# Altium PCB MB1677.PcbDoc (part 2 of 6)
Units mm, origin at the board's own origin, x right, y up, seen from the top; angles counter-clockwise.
Board outline 78 x 105 mm, 6 copper layers (Top Layer, Signal Layer 1, Signal Layer 2, Signal Layer 3, Signal Layer 4, Bottom Layer), stack 1.574 mm thick; 404 components, 325 nets, 1691 pads, 961 vias.
Unrouted connection lines stored in the file: 9.
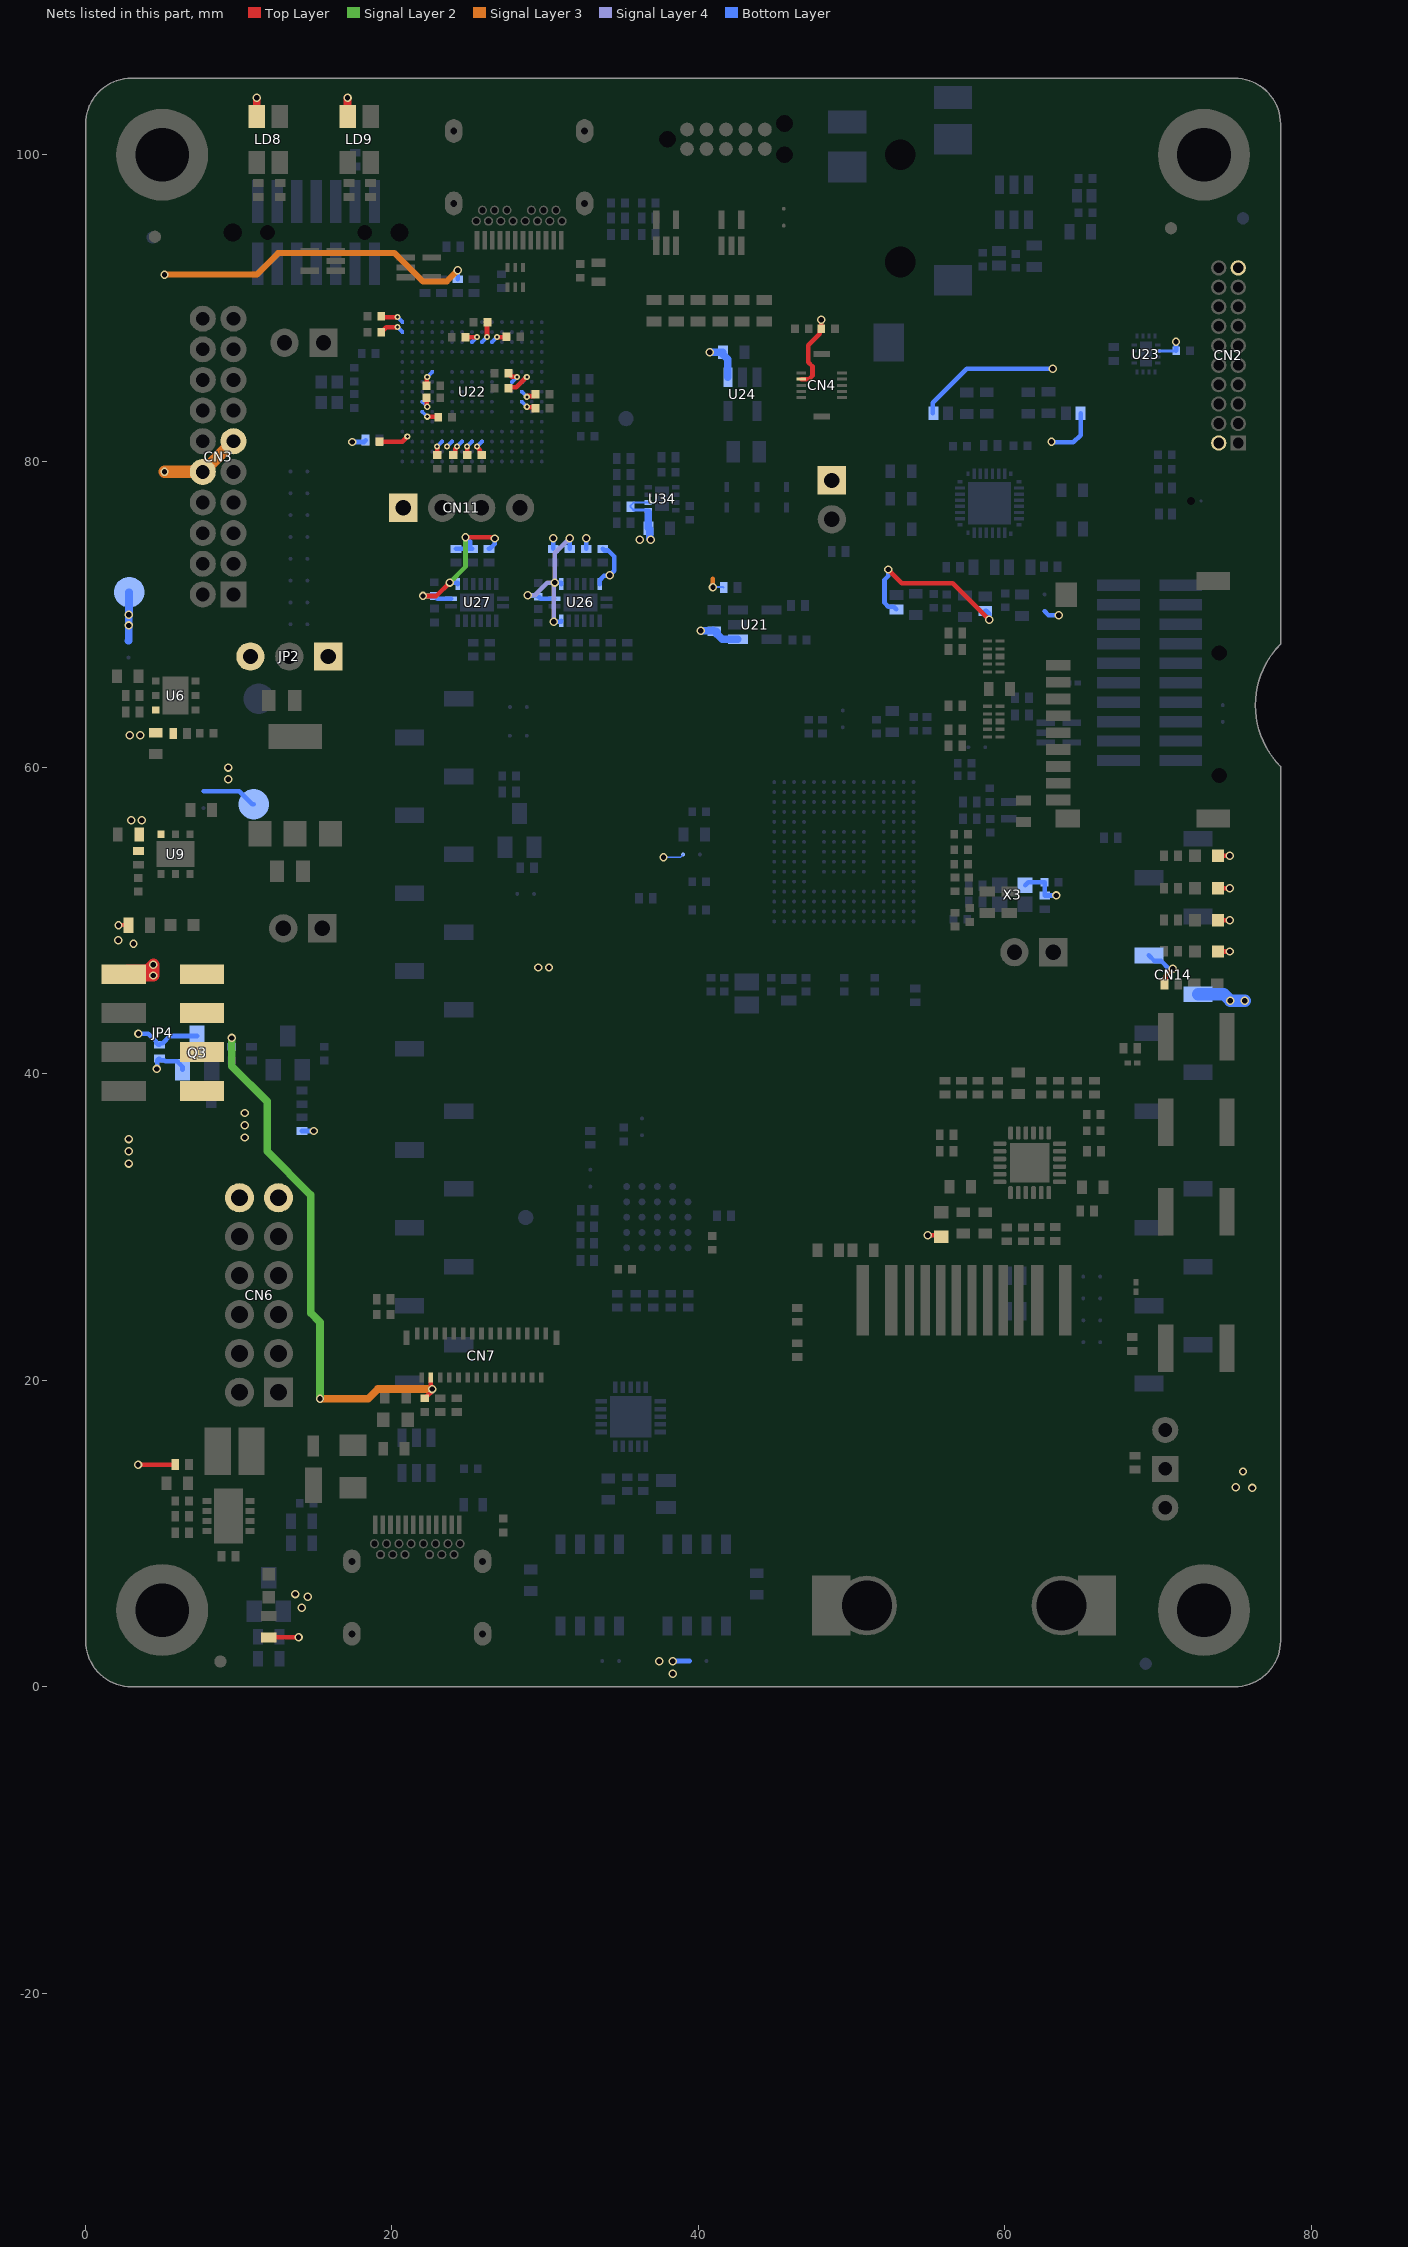
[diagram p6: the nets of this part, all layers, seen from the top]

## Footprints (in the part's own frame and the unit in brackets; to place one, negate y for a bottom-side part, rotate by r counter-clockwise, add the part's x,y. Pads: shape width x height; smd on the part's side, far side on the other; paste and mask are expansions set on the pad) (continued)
ICC_QFN32-EPAD_4X4_P040 [mm] "MCD-03196"
  rect 0.22x0.3 smd mask+0.05: 1(-1.4,-2) 8(1.4,-1.925) 17(1.4,1.925) 24(-1.4,1.925)
  rect 0.22x0.66 smd mask+0.05: 2(-1,-1.925) 3(-0.6,-1.925) 4(-0.2,-1.925) 5(0.2,-1.925) 6(0.6,-1.925) 7(1,-1.925) 18(1,1.925) 19(0.6,1.925) 20(0.2,1.925) 21(-0.2,1.925) 22(-0.6,1.925) 23(-1,1.925)
  rect 0.3x0.22 smd mask+0.05: 9(1.925,-1.4) 16(1.925,1.4) 25(-1.925,1.4) 32(-1.925,-1.4)
  rect 0.66x0.22 smd mask+0.05: 10(1.925,-1) 11(1.925,-0.6) 12(1.925,-0.2) 13(1.925,0.2) 14(1.925,0.6) 15(1.925,1) 26(-1.925,1) 27(-1.925,0.6) 28(-1.925,0.2) 29(-1.925,-0.2) 30(-1.925,-0.6) 31(-1.925,-1)
  rect 2.8x2.8 smd mask+0.05: 33(0,0)
  Top Layer region: 1.29,-2.255 1.29,-1.595 1.35,-1.595 1.51,-1.755 1.51,-2.255
  Top Layer region: -1.29,-2.255 -1.29,-1.595 -1.35,-1.595 -1.51,-1.755 -1.51,-2.255
  Top Layer region: -2.255,-1.29 -1.595,-1.29 -1.595,-1.35 -1.755,-1.51 -2.255,-1.51
  Top Layer region: -2.255,1.29 -1.595,1.29 -1.595,1.35 -1.755,1.51 -2.255,1.51
  Top Layer region: 2.255,1.29 1.595,1.29 1.595,1.35 1.755,1.51 2.255,1.51
  Top Layer region: 2.255,-1.29 1.595,-1.29 1.595,-1.35 1.755,-1.51 2.255,-1.51
  Top Layer region: 1.29,2.255 1.29,1.595 1.35,1.595 1.51,1.755 1.51,2.255
  Top Layer region: -1.29,2.255 -1.29,1.595 -1.35,1.595 -1.51,1.755 -1.51,2.255
  silkscreen extent -2.25,-2.25 -1.68,-1.68, body extent -2.01,-2.01 2,2.01, height 0.91
ICC_SOT23-5L_H1P45 [mm]
  rect 0.6x1.3 smd mask+0.05: 1(-0.95,-1.1) 2(0,-1.1) 3(0.95,-1.1) 4(0.95,1.1) 5(-0.95,1.1)
  silkscreen extent -1.75,-1.68 1.6,0.97, body extent -1.52,-1.25 1.52,1.25, height 1.45
ICC_UFBGA201_176+25_10X10_P065 [mm] "IPC"
  round 0.25 smd mask+0.05: A1(-4.55,4.55) A2(-3.9,4.55) A3(-3.25,4.55) A4(-2.6,4.55) A5(-1.95,4.55) A6(-1.3,4.55) A7(-0.65,4.55) A8(0,4.55) A9(0.65,4.55) A10(1.3,4.55) A11(1.95,4.55) A12(2.6,4.55) A13(3.25,4.55) A14(3.9,4.55) A15(4.55,4.55) B1(-4.55,3.9) B2(-3.9,3.9) B3(-3.25,3.9) B4(-2.6,3.9) B5(-1.95,3.9) B6(-1.3,3.9) B7(-0.65,3.9) B8(0,3.9) B9(0.65,3.9) B10(1.3,3.9) B11(1.95,3.9) B12(2.6,3.9) B13(3.25,3.9) B14(3.9,3.9) B15(4.55,3.9) C1(-4.55,3.25) C2(-3.9,3.25) C3(-3.25,3.25) C4(-2.6,3.25) C5(-1.95,3.25) C6(-1.3,3.25) C7(-0.65,3.25) C8(0,3.25) C9(0.65,3.25) C10(1.3,3.25) C11(1.95,3.25) C12(2.6,3.25) C13(3.25,3.25) C14(3.9,3.25) C15(4.55,3.25) D1(-4.55,2.6) D2(-3.9,2.6) D3(-3.25,2.6) D4(-2.6,2.6) D5(-1.95,2.6) D6(-1.3,2.6) D7(-0.65,2.6) D8(0,2.6) D9(0.65,2.6) D10(1.3,2.6) D11(1.95,2.6) D12(2.6,2.6) D13(3.25,2.6) D14(3.9,2.6) D15(4.55,2.6) E1(-4.55,1.95) E2(-3.9,1.95) E3(-3.25,1.95) E4(-2.6,1.95) E12(2.6,1.95) E13(3.25,1.95) E14(3.9,1.95) E15(4.55,1.95) F1(-4.55,1.3) F2(-3.9,1.3) F3(-3.25,1.3) F4(-2.6,1.3) F6(-1.3,1.3) F7(-0.65,1.3) F8(0,1.3) F9(0.65,1.3) F10(1.3,1.3) F12(2.6,1.3) F13(3.25,1.3) F14(3.9,1.3) F15(4.55,1.3) G1(-4.55,0.65) G2(-3.9,0.65) G3(-3.25,0.65) G4(-2.6,0.65) G6(-1.3,0.65) G7(-0.65,0.65) G8(0,0.65) G9(0.65,0.65) G10(1.3,0.65) G12(2.6,0.65) G13(3.25,0.65) G14(3.9,0.65) G15(4.55,0.65) H1(-4.55,0) H2(-3.9,0) H3(-3.25,0) H4(-2.6,0) H6(-1.3,0) H7(-0.65,0) H8(0,0) H9(0.65,0) H10(1.3,0) H12(2.6,0) H13(3.25,0) H14(3.9,0) H15(4.55,0) J1(-4.55,-0.65) J2(-3.9,-0.65) J3(-3.25,-0.65) J4(-2.6,-0.65) J6(-1.3,-0.65) J7(-0.65,-0.65) J8(0,-0.65) J9(0.65,-0.65) J10(1.3,-0.65) J12(2.6,-0.65) J13(3.25,-0.65) J14(3.9,-0.65) J15(4.55,-0.65) K1(-4.55,-1.3) K2(-3.9,-1.3) K3(-3.25,-1.3) K4(-2.6,-1.3) K6(-1.3,-1.3) K7(-0.65,-1.3) K8(0,-1.3) K9(0.65,-1.3) K10(1.3,-1.3) K12(2.6,-1.3) K13(3.25,-1.3) K14(3.9,-1.3) K15(4.55,-1.3) L1(-4.55,-1.95) L2(-3.9,-1.95) L3(-3.25,-1.95) L4(-2.6,-1.95) L12(2.6,-1.95) L13(3.25,-1.95) L14(3.9,-1.95) L15(4.55,-1.95) M1(-4.55,-2.6) M2(-3.9,-2.6) M3(-3.25,-2.6) M4(-2.6,-2.6) M5(-1.95,-2.6) M6(-1.3,-2.6) M7(-0.65,-2.6) M8(0,-2.6) M9(0.65,-2.6) M10(1.3,-2.6) M11(1.95,-2.6) M12(2.6,-2.6) M13(3.25,-2.6) M14(3.9,-2.6) M15(4.55,-2.6) N1(-4.55,-3.25) N2(-3.9,-3.25) N3(-3.25,-3.25) N4(-2.6,-3.25) N5(-1.95,-3.25) N6(-1.3,-3.25) N7(-0.65,-3.25) N8(0,-3.25) N9(0.65,-3.25) N10(1.3,-3.25) N11(1.95,-3.25) N12(2.6,-3.25) N13(3.25,-3.25) N14(3.9,-3.25) N15(4.55,-3.25) P1(-4.55,-3.9) P2(-3.9,-3.9) P3(-3.25,-3.9) P4(-2.6,-3.9) P5(-1.95,-3.9) P6(-1.3,-3.9) P7(-0.65,-3.9) P8(0,-3.9) P9(0.65,-3.9) P10(1.3,-3.9) P11(1.95,-3.9) P12(2.6,-3.9) P13(3.25,-3.9) P14(3.9,-3.9) P15(4.55,-3.9) R1(-4.55,-4.55) R2(-3.9,-4.55) R3(-3.25,-4.55) R4(-2.6,-4.55) R5(-1.95,-4.55) R6(-1.3,-4.55) R7(-0.65,-4.55) R8(0,-4.55) R9(0.65,-4.55) R10(1.3,-4.55) R11(1.95,-4.55) R12(2.6,-4.55) R13(3.25,-4.55) R14(3.9,-4.55) R15(4.55,-4.55)
  silkscreen extent -5.22,-5.07 5.07,5.23, body extent -5.07,-5.07 5.07,5.07, height 0.61
ICC_UFQFN16-EPAD_2P6X1P8_P040 [mm]
  rect 0.2x0.35 smd mask+0.05: 1(-0.6,-0.775) 2(-0.2,-0.775) 3(0.2,-0.775) 4(0.6,-0.775) 9(0.6,0.775) 10(0.2,0.775) 11(-0.2,0.775) 12(-0.6,0.775)
  rect 0.35x0.2 smd mask+0.05: 5(1.175,-0.6) 6(1.175,-0.2) 7(1.175,0.2) 8(1.175,0.6) 13(-1.175,0.6) 14(-1.175,0.2) 15(-1.175,-0.2) 16(-1.175,-0.6)
  rect 1.6x0.8 smd mask+0.05: 17(0,0)
  silkscreen extent -1.33,-0.92 1.33,0.92, body extent -1.33,-0.92 1.33,0.92, height 0.56
ICC_VQFN24-EPAD_4X4_P050 [mm]
  rrect50% 0.85x0.3 smd mask+0.05: 1(-1.95,1.25) 2(-1.95,0.75) 3(-1.95,0.25) 4(-1.95,-0.25) 5(-1.95,-0.75) 6(-1.95,-1.25) 13(1.95,-1.25) 14(1.95,-0.75) 15(1.95,-0.25) 16(1.95,0.25) 17(1.95,0.75) 18(1.95,1.25)
  rrect50% 0.3x0.85 smd mask+0.05: 7(-1.25,-1.95) 8(-0.75,-1.95) 9(-0.25,-1.95) 10(0.25,-1.95) 11(0.75,-1.95) 12(1.25,-1.95) 19(1.25,1.95) 20(0.75,1.95) 21(0.25,1.95) 22(-0.25,1.95) 23(-0.75,1.95) 24(-1.25,1.95)
  rect 2.6x2.6 smd paste-10 mask+0.05: EP(0,0)
  silkscreen extent -2,-2 2,2, body extent -2.05,-2.05 2.05,2.05, height 1.1
ICC_WSON8-EPAD_2X2_P050 [mm] "MCD-02194"
  rect 0.5x0.3 smd paste+0 mask+0.05: 1(-0.9,0.75) 2(-0.9,0.25) 3(-0.9,-0.25) 4(-0.9,-0.75) 5(0.9,-0.75) 6(0.9,-0.25) 7(0.9,0.25) 8(0.9,0.75)
  rect 0.9x1.6 smd paste+0 mask+0.05: 9(0,0)
  silkscreen extent -0.5,-1 0.5,1, body extent -1,-1 1,1, height 0.81
IND_0402_MURATA_BLM15H_H0P5 [mm] "MCD-01610"
  rect 0.65x0.9 smd mask+0.05: 1(-0.475,0) 2(0.475,0)
  body extent -0.53,-0.28 0.53,0.28, height 0.55
L0603 [mm]
  rect 0.8x0.95 smd mask+0.05: 1(-0.8,0) 2(0.8,0)
  silkscreen extent -1.33,-0.6 1.33,0.6, body extent -0.87,-0.47 0.87,0.47, height 0.95
L0805_H0P9 [mm]
  rect 1.1x1.6 smd mask+0.05: 1(-0.75,0) 2(0.75,0)
  silkscreen extent -0.08,-0.7 0.08,0.7, body extent -1.07,-0.7 1.07,0.7, height 1.2
L1210_LQH [mm]
  rect 1.7x3.1 smd mask+0.05: 1(-1.1,0) 2(1.1,0)
  silkscreen extent -2.05,-1.65 2.05,1.65, body extent -1.75,-1.35 1.75,1.35, height 2
LCD_DRAWING_FRIDA_FRD154BP2902-D-CTQ [mm] "MCD-01797"
  silkscreen extent -29.75,-65.09 6.95,2.75, body extent -29.75,-61.6 6.85,2.65, height 3
LED_0603_OSRAM_LB-Q39G-L2OO-35-1_BLUE_1A2K_H0P4 [mm]
  rect 0.8x0.8 smd mask+0.05: 1(-0.75,0) 2(0.75,0)
  silkscreen extent -0.85,-0.53 1.28,0.53, body extent -0.85,-0.45 0.85,0.45, height 0.6
LED_0603_OSRAM_LG-Q396-PS-35_GREEN_1A2K_H0P4 [mm]
  rect 0.8x0.8 smd mask+0.05: 1(-0.75,0) 2(0.75,0)
  silkscreen extent -0.85,-0.53 1.28,0.53, body extent -0.85,-0.45 0.85,0.45, height 0.6
LED_0603_OSRAM_LO-Q976-PS-25_ORANGE_1A2K_H0P8 [mm]
  rect 0.8x0.8 smd mask+0.05: 1(-0.75,0) 2(0.75,0)
  silkscreen extent -0.85,-0.53 1.28,0.53, body extent -0.85,-0.45 0.85,0.45, height 0.8
LED_0603_VISHAY_VLMS1300-GS08_RED_1A2K_H0P8 [mm]
  rect 0.8x0.8 smd mask+0.05: 1(-0.75,0) 2(0.75,0)
  silkscreen extent -0.85,-0.53 1.28,0.53, body extent -0.85,-0.45 0.85,0.45, height 0.8
LED_0603_VISHAY_VLMTG1300-GS08_GREEN_1A2K_H0P8 [mm]
  rect 0.8x0.8 smd mask+0.05: 1(-0.75,0) 2(0.75,0)
  silkscreen extent -0.85,-0.53 1.28,0.53, body extent -0.85,-0.45 0.85,0.45, height 0.8
LED_BI-GR_WE-150141SV73110 [mm] "MCD-02631"
  rect 1.1x1.5 smd mask+0.05: 1(-0.75,1.5) 2(0.75,1.5) 3(-0.75,-1.5) 4(0.75,-1.5)
  silkscreen extent -1.65,-1.85 1.5,1.7, body extent -1.5,-1.85 1.5,1.85, height 2.1
LOGO_ETIQUETTE [mm]
  silkscreen extent 0,0 27,10
MIC_STM_MP23DB01MMTR [mm]
  rect 0.725x0.522 smd mask+0.05: 1(-0.838,1.364) 2(-0.838,0.542) 4(0.838,0.542) 5(0.838,1.364)
  round 0.2 smd mask+0.05: 3(0,-1.373)
  round 0 hole 0.5 unplated mask+0.05: 6(0,-0.71)
  Top Layer circle w0.3: c0,-0.71 r0.663
  silkscreen extent -1.33,-1.75 1.33,1.75, body extent -1.33,-1.76 1.33,1.75, height 1.09
MIRE_PLACE_SMD_0P8MM [mm]
  round 0.8 smd paste-10 mask+0.2: 1(0,0)
  Top Layer keep-out circle w0.01: c0,0 r0.804
MOS_SOT23 [mm]
  rect 1x1.4 smd mask+0.05: 1(-0.95,-1.1) 2(0.95,-1.1) 3(0,1.1)
  silkscreen extent -1.63,-0.82 1.63,0.82, body extent -1.56,-1.25 1.56,1.25, height 1.1
MOS_SOT23-5L [mm]
  rect 0.6x1.3 smd mask+0.05: 1(-0.95,-1.1) 2(0,-1.1) 3(0.95,-1.1) 4(0.95,1.1) 5(-0.95,1.1)
  silkscreen extent -1.6,-0.95 1.6,0.97, body extent -1.52,-1.25 1.52,1.25, height 1.45
NPN_SOT23 [mm]
  rect 1x1.4 smd mask+0.05: 1(-0.95,-1.1) 2(0.95,-1.1) 3(0,1.1)
  silkscreen extent -1.63,-0.82 1.63,0.82, body extent -1.56,-1.25 1.56,1.25, height 1.1
OSC_NDK_NZ2520SB_4P [mm]
  rect 1x1 smd mask+0.05: 1(-0.825,-0.625) 2(0.825,-0.625) 3(0.825,0.625) 4(-0.825,0.625)
  silkscreen extent -1.43,-1.22 1.2,1.05, body extent -1.3,-1.05 1.3,1.05, height 0.91
PowerFLAT_5x6 [mm] "MCD-02152"
  rect 0.65x1.25 smd mask+0.05: 1(1.905,2.675) 2(0.635,2.675) 3(-0.635,2.675) 4(-1.905,2.675) 5(-1.905,-2.675) 6(-0.635,-2.675) 7(0.635,-2.675) 8(1.905,-2.675)
  Top Layer region: -0.2,-3.3 -0.95,-3.3 -0.95,-2.75 -1.575,-2.75 -1.575,-3.3 -2.3,-3.3 -2.3,-2.3 -2.7,-2.3 -2.7,-1.5 -2.3,-1.5 -2.3,0.15 -2.7,0.15 -2.7,0.975 -2.3,0.975 -2.3,1.15 -0.2,1.15
  Top Layer region: 0.2,-3.3 0.95,-3.3 0.95,-2.75 1.575,-2.75 1.575,-3.3 2.3,-3.3 2.3,-2.3 2.7,-2.3 2.7,-1.5 2.3,-1.5 2.3,0.15 2.7,0.15 2.7,0.975 2.3,0.975 2.3,1.15 0.2,1.15
  silkscreen extent -2.5,-3 2.5,3, body extent -2.6,-3.08 2.6,3.07, height 1
PTH_M1261-3005-N_3P5X6_M3_H14 [mm]
  round 6 hole 3.5 mask+0.05: 1(0,0)
  silkscreen extent -3.25,-3.25 3.25,3.25, body extent -2.5,-2.5 2.5,2.5, height 14
R0402 [mm]
  rect 0.51x0.7 smd mask+0.05: 1(-0.45,0) 2(0.45,0)
  silkscreen extent 0,-0.3 0,0.3, body extent -0.52,-0.3 0.52,0.3, height 0.4
R0603 [mm]
  rect 0.64x1 smd mask+0.05: 1(-0.7,0) 2(0.7,0)
  silkscreen extent -1.05,-0.58 1.05,0.58, body extent -0.9,-0.5 0.9,0.5, height 0.56
R0805_H0P5 [mm] "MCD-01537"
  rect 0.85x1.3 smd mask+0.05: 1(-0.875,0) 2(0.875,0)
  silkscreen extent -0.33,-0.67 0.33,0.67, body extent -1.05,-0.68 1.05,0.68, height 0.6
REG_SOT223-TAB [mm]
  rect 1.5x1.65 smd mask+0.05: 1(-2.3,-3.175) 2(0,-3.175) 3(2.3,-3.175)
  rect 3.5x1.65 smd mask+0.05: 4(0,3.175)
  silkscreen extent -3.35,-2.15 3.35,2.12, body extent -3.35,-3.48 3.35,3.48, height 1.8
SOLDER-BRIDGE_R0603-0R [mil]
  round 10 smd paste-393.7: 1(-19.68,0) 2(23.62,0)
  Top Layer region: -5.91,19.68 13.78,0 -5.91,-19.68 47.24,-19.68 47.24,19.68 -5.91,19.68
  Top Layer region: -47.24,-19.68 -47.24,19.68 -15.75,19.68 3.94,0 -15.75,-19.68 -47.24,-19.68
  silkscreen extent -50,-23 50,23, body extent -36,-20 36,20, height 22
SWI_C&K_KSC321GLFS_BLACK [mm] "BLACK"
  rect 3.1x1 smd mask+0.05: 1(-4.45,2) 2(4.45,2) 3(-4.45,-2) 4(4.45,-2)
  silkscreen extent -3.25,-3.25 3.25,3.25, body extent -5,-3.25 5,3.25, height 3.5
SWI_C&K_KSC721JLFS_BLUE [mm] "MCD-01800"
  rect 3.1x1 smd mask+0.05: 1(-2.8,2) 2(2.8,2) 3(-2.8,-2) 4(2.8,-2)
  silkscreen extent -3.25,-3.25 3.25,3.25, body extent -3.4,-3.25 3.4,3.25, height 4.3
SWI_EAO_09-03290-01_EXTENDED_STRAIGHT_BLACK [mm]
  rect 1.7x1.7 hole 0.9 mask+0.05: 1(0,0)
  round 1.7 hole 0.9 mask+0.05: 2(0,-2.54) 3(0,2.54)
  silkscreen extent -1.25,-5 1.25,5, body extent -1.25,-5 1.25,5, height 7.9
TP_SMD_1MM [mm]
  round 1 smd paste-10 mask+0.05: 1(0,0)
  silkscreen extent -0.7,-0.7 0.7,0.7
TP_SMD_2MM [mm]
  round 2 smd paste-10 mask+0.05: 1(0,0)
  silkscreen extent -1.2,-1.2 1.2,1.2

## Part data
B1: library part MCD-01800, "Switch HW BLUE High4.3mm 2.25 Newtons, BEND type", Manufacturer=C&K, Manufacturer_Part_Number=KSC721JLFS, Package=6.2x6.2mm
B2: library part MCD-00175, "Switch HW BLACK High3.5mm 2Newtons", Manufacturer=C&K, Manufacturer_Part_Number=KSC321GLFS, Package=6.2x10mm
C1 C2 C3 C4 C5 C6 C7 C8 C9 C10 C11 C12 C13 C14 C15 C16 C17 C18 C19 C26 C29 C30 C31 C34 C35 C44 C47 C48 C50 C54 C55 C58 C63 C68 C73 C86 C87 C89 C90 C91 C92 C93 C97 C98 C99 C101 C103 C106 C107 C108 C109 C110 C111 C112 C117 C118 C119 C127: library part MCD-00006, "Capacitor, MLCC, 100nF, 16V, X7R, +/-10%, 0402, T=0.5mm", Manufacturer=YAGEO, Manufacturer_Part_Number=CC0402KRX7R7BB104, Package=0402
C20 C21 C78: library part MCD-02198, "Capacitor, MLCC, 10nF, 50V, X7R, +/-10%, 0402, T=0.5mm", Manufacturer=YAGEO, Manufacturer_Part_Number=CC0402KRX7R9BB103, Package=0402
C22 C25 C27 C28 C56 C69 C74 C79 C84 C88 C94 C126: library part MCD-00009, "Capacitor, MLCC, 4.7uF, 16V, X5R, +/-10%, 0603, T=0.8mm", Manufacturer=YAGEO, Manufacturer_Part_Number=CC0603KRX5R7BB475, Package=0603
C23: library part MCD-01721, "Capacitor, 4.7uF, 10V, X5R, 10%, 0603, T=0.8mm", Manufacturer=YAGEO, Manufacturer_Part_Number=CC0603KRX5R6BB475, Package=0603
C24 C32: library part MCD-00014, "Capacitor, MLCC, 10uF, 25V, X5R, 10%, 0805, T=0,85mm", Manufacturer=YAGEO, Manufacturer_Part_Number=CC0805KRX5R8BB106, Package=0805
C33 C36 C62 C100: library part MCD-01722, "Capacitor, 1uF, 10V, X5R, 10%, 0402, T=0.5mm", Manufacturer=YAGEO, Manufacturer_Part_Number=CC0402KRX5R6BB105, Package=0402
C37 C40 C41 C42 C45 C46: library part MCD-02119, "Capacitor, MLCC, 100nF, 6V3, X5R, +/-10%, 0603, T=0.8mm", Manufacturer=KEMET, Manufacturer_Part_Number=C0603C104K9PACTU, Package=0603
C38 C67: library part MCD-00095, "Capacitor, MLCC, 1uF, 25V, X5R, +/-10%, 0402, T=0.5mm", Manufacturer=MURATA, Manufacturer_Part_Number=GRM155R61E105KA12, Package=0402
C39 C128 C129: library part MCD-00724, "Capacitor, MLCC, 470pF, 50V, NPO, +/-5%, 0402, T=0.5mm", Manufacturer=YAGEO, Manufacturer_Part_Number=CC0402JRNPO9BN471, Package=0402
C43: library part MCD-01124, "Capacitor, MLCC, 10µF, 10V, X5R, 10%, 0603, T=0.8mm", Manufacturer=MURATA, Manufacturer_Part_Number=GRM188R61A106KAAL, Package=0603
C49 C52 C121: library part MCD-01099, "Capacitor,100nF,50V,X7R,10%,0603", Manufacturer=YAGEO, Manufacturer_Part_Number=CC0603KRX7R9BB104, Package=0603
C51: library part MCD-00013, "Capacitor, MLCC, 4.7uF, 50V, X7R, 10%, 1206, T=1,27mm", Manufacturer=AVX, Manufacturer_Part_Number=12065C475KAT2A, Package=1206
C53 C60 C64 C66: library part MCD-00099, "Capacitor, MLCC, 10uF, 10V, X5R, +/-10%, 0603, T=0.8mm", Manufacturer=MURATA, Manufacturer_Part_Number=GRM188R61A106KE69D, Package=0603
C57: library part MCD-00205, "Capacitor, MLCC, 100pF, 50V, NPO, +/-5%, 0402, T=0.5mm", Manufacturer=YAGEO, Manufacturer_Part_Number=CC0402JRNPO9BN101, Package=0402
C59 C70 C77: library part MCD-02606, "Capacitor, MLCC, 2.2uF, 6.3V, X5R, +/-10%, 0402, T=0.5mm", Manufacturer=YAGEO, Manufacturer_Part_Number=CC0402KRX5R5BB225, Package=0402
C61 C65: library part MCD-02355, "Capacitor, MLCC, 100nF, 25V, X7R, +/-10%, 0402, T=0.5mm", Manufacturer="WALSIN TECHNOLOGY CORPORATION", Manufacturer_Part_Number=0402B104K250CT, Package=0402
C71 C72: library part MCD-01774, "Capacitor, MLCC, 2.7pF, 50V, NPO, +/-0.1pF, 0402, T=0.5mm", Manufacturer=YAGEO, Manufacturer_Part_Number=CC0402BRNPO9BN2R7, Package=0402
C75: "Capacitor, MLCC, 100nF, 16V, X7R, +/-10%, 0402, T=0.5mm", Manufacturer=YAGEO, Manufacturer_Part_Number=CC0402KRX7R7BB104, Package=0402
C76 C81 C83: library part MCD-00012, "Capacitor, MLCC, 2.2uF, 10V, X5R, +/- 10%, 0603, T=0.8mm", Manufacturer=YAGEO, Manufacturer_Part_Number=CC0603KRX5R6BB225, Package=0603
C80: library part MCD-02372, "Capacitor, MLCC, 2.2uF, 25V, X7R, +/-10%, 0805, T=1,25mm", Alternate_Manufacturer=N/A, Manufacturer=MURATA, Manufacturer_Part_Number=GRM21BR71E225KE11L, Package=0805
C82 C105: library part MCD-00010, "Capacitor, MLCC, 1uF, 16V, X5R, +/-10%, 0603, T=0.8mm", Manufacturer=YAGEO, Manufacturer_Part_Number=CC0603KRX5R7BB105, Package=0603
C95 C116: library part MCD-01356, "Capacitor, MLCC, 4.7uF, 6V3, X5R, +/-20%, 0402, T=0,5mm", Alternate_Manufacturer=MURATA, Alternate_Manufacturer_Part_Number=GRM155R60J475ME87, Manufacturer_Part_Number=GRM155R60J475ME47, Package=0402
C96 C115: library part MCD-01823, "Capacitor,MLCC, 2.2uF, 6V3, X5R,+/-10%, 0402, T=0.5mm", Manufacturer=MURATA, Manufacturer_Part_Number=GRM155R60J225KE95D, Package=0402
C102 C104: library part MCD-01775, "Capacitor, MLCC, 3.3pF, 50V, NPO, +/-0.1pF, 0402, T=0.5mm", Manufacturer=YAGEO, Manufacturer_Part_Number=CC0402BRNPO9BN3R3, Package=0402
C113: library part MCD-01225, "Capacitor, MLCC, 220pF, 50V, NPO, +/-5%, 0402, T=0,5mm", Manufacturer=YAGEO, Manufacturer_Part_Number=CC0402JRNPO9BN221, Package=0402
C114: library part MCD-01355, "Capacitor, MLCC, 10uF, 4V, X5R, +/-20%, 0402, T=0,5mm", Manufacturer=MURATA, Manufacturer_Part_Number=GRM155R60G106ME44, Package=0402
C120 C123: library part MCD-01579, "Capacitor, MLCC, 330pF, 50V, NPO, +/-5%, 0402, T=0,5mm", Manufacturer=YAGEO, Manufacturer_Part_Number=CC0402JRNPO9BN331, Package=0402
C122: library part MCD-00015, "Capacitor, MLCC, 10pF, 50V, NPO, 5%, 0402, T=0,5mm", Manufacturer=YAGEO, Manufacturer_Part_Number=CC0402JRNPO9BN100, Package=0402
C124 C125: library part MCD-00211, "Capacitor, MLCC, 100nF, 16V, X7R, 10%, 0603, T=0,8mm", Manufacturer=YAGEO, Manufacturer_Part_Number=CC0603KRX7R7BB104, Package=0603
CN1: library part MCD-00031, "Tag_Connector Header, 10x2, No legs", Manufacturer=N/A
CN2: library part MCD-00147, "Socket for MB1299, 10x2, 1.27mm, VR, TH, Height 4.30mm/2.40mm", Alternate_Manufacturer=JIUBABA, Alternate_Manufacturer_Part_Number=234220S1410, Manufacturer="AMPHENOL ICC", Manufacturer_Part_Number=20021311-00020T4LF
CN3: library part MCD-00309, "Socket 10x2, 2.00mm, RA, TH, Height 6.35mm/2.29mm", Alternate_Manufacturer=JIUBABA;CONNECT, Alternate_Manufacturer_Part_Number=FH200020C-12300;CNT-F200-2*10-GD-635/2.3, Manufacturer=SAMTEC, Manufacturer_Part_Number=SQT-110-01-F-D-RA
CN4: library part MCD-00021, "Socket FCC/FPC, 5x2, 0.4mm, VR, SMT, 0.98mm, Frida touch panel", Manufacturer=HIROSE, Manufacturer_Part_Number="DF37NB-10DS-0.4V (5x)"
CN5: library part MCD-00653, "Connector_uSD Card, Top Mnt Push-Push", Manufacturer=ATOM
CN6: library part MCD-00308, "Socket, 6x2, 2.54mm, TH, RA, Height 8.51mm/7.62mm", Manufacturer=SAMTEC, Manufacturer_Part_Number=SSW-106-02-F-D-RA
CN7: library part MCD-01798, "Socket FCC/FPC, 29pins, 0.6mm, SMT, for FRIDA LCD (replacement of obsolete component MCD-00020 FH26-29S-0.3SHW)", Manufacturer=HIROSE, Manufacturer_Part_Number=FH26W-29S-0.3SHW(60)
CN8: library part MCD-02475, "connector_RJ45, 10/100 Ethernet integrated MAG with integrate Green and Yellow LED, T= 13.61mm", Alternate_Manufacturer=N/A, Manufacturer=PENGHUI, Manufacturer_Part_Number=RMT-119A-12F6-GY-02
CN9: library part MCD-00263, "Connector Jack Socket Stereo 3.5mm, 4 pins, RA, SMT, Black", Manufacturer=QIAOD, Manufacturer_Part_Number=PJ-3028B-4P
CN10 CN17: library part MCD-02273, "USB_TypeC, 24pins, RA, TH, T=1.9mm (USB certified)", Manufacturer="WURTH ELEKTRONIK", Manufacturer_Part_Number=632723300011
CN11: library part MCD-00029, "Header, 4x1, 2,54mm, VR, TH, Height 5.84mm/2.54mm", Manufacturer=SAMTEC, Manufacturer_Part_Number=TSW-104-07-G-S
CN12: library part MCD-01226, "Header, 5x2, 1.27mm, VR, SMD, T=5.97mm/3.05mm", Manufacturer=SAMTEC, Manufacturer_Part_Number=FTSH-105-01-L-DV-K
CN13: library part MCD-02342, "Socket, 10x1, 2.54mm, VR, SMD, T=7.37mm", Manufacturer=SAMTEC, Manufacturer_Part_Number=SSM-110-L-SV
CN14 CN15: library part MCD-02345, "Socket, 8x1, 2.54mm, VR, SMD, T=7.37mm", Manufacturer=SAMTEC, Manufacturer_Part_Number=SSM-108-L-SV
CN16: library part MCD-02346, "Socket, 6x1, 2.54mm, VR, SMD, T=7.37mm", Manufacturer=SAMTEC, Manufacturer_Part_Number=SSM-106-L-SV
CN18: library part MCD-00557, "Header, 10x2, 1.27mm, VR, SMD, T=3.05mm", Manufacturer=SAMTEC, Manufacturer_Part_Number=FTSH-110-01-L-DV
D1: library part MCD-00033, "Low Drop power Schottky rectifier(1A, 40V, 0.4V)", Manufacturer=STMICROELECTRONICS, Manufacturer_HQ_COO=EU, Package=DO216-AA
D2 D3 D4: library part MCD-01677, "Small signal Schottky diodes", Manufacturer=STMICROELECTRONICS, Manufacturer_HQ_COO=EU, Manufacturer_Part_Number=BAT54KFILM, Package=SOD523
H1 H2 H3 H4: library part MCD-00035, "POSITION HOLE C6D3R5", Manufacturer=N/A, Manufacturer_HQ_COO=Unknown, Manufacturer_Part_Number=n/a
JP1 JP5: library part MCD-00045, "Header, 2x1, 2,54mm, VR, TH, Height 5.84mm/2.54mm", Alternate_Manufacturer="JIUBABA; LIANYI", Alternate_Manufacturer_Part_Number=313102S111116;313102S111116, Manufacturer=SAMTEC, Manufacturer_Part_Number=TSW-102-07-G-S
JP2: library part MCD-00684, "Header, 3x1, 2,54mm, VR, TH, Height 5.84mm/2.54mm - Shunt Fitted 1-2 by default", Manufacturer=SAMTEC, Manufacturer_Part_Number=TSW-103-07-F-S
JP3: library part MCD-00045, "Header, 2x1, 2,54mm, VR, TH, Height 5.84mm/2.54mm", Manufacturer=SAMTEC, Manufacturer_Part_Number=TSW-102-07-G-S
JP4: library part MCD-00044, "Header, 4x2, 2,54mm, VR, SMT, Height 5.84mm/2.54mm", Manufacturer=SAMTEC, Manufacturer_Part_Number=TSM-104-01-G-DV
JP6: library part MCD-00045, "Header, 2x1, 2,54mm, VR, TH, Height 5.84mm/2.54mm", Alternate_Manufacturer=JIUBABA, Alternate_Manufacturer_Part_Number=313102S111116, Manufacturer=SAMTEC, Manufacturer_Part_Number=TSW-102-07-G-S
L1: library part MCD-02437, "Ferrite bead, 600R@100MHz, +/-25%, 500mA, 380mR, 0603, T=0.8mm", Alternate_Manufacturer=N/A, Manufacturer=MURATA, Manufacturer_Part_Number=BLM18AG601SN1D, Package=0603
L2: library part MCD-00047, "SMD Chip ferrite bead, 600R@100MHz +/-25%, 350mA, 500mohm DC, 0603, T=0.8mm", Manufacturer=TAI-TECH, Manufacturer_Part_Number=FCM1608KF-601T03, Package=0603
L3: library part MCD-00048, "FIXED IND 4.7UH 1A 180 MOHM 30% SMD", Manufacturer=MURATA, Manufacturer_Part_Number=LQH32PN4R7NN0L, Package=1210
L4: library part MCD-03791, "Inductor 2.2uH, +/-20%, 1.8A, 0.138Ω, 0805", Manufacturer=MURATA, Manufacturer_Part_Number=DFE21CCN2R2MELL, Package=0805
L5 L6 L7 L8 L9 L10: library part MCD-02381, "Ferrite bead, 10R @100MHz, 5R, 0.75A, 0.07R, 0402, T=0.22mm", Manufacturer=MURATA, Manufacturer_Part_Number=BLM02AX100SN1D, Package=0402
LD1 LD6 LD7: library part MCD-00588, "LED Green, 0603 SMD, Forward Voltage Typ=2V, Max=2.5V", Alternate_Manufacturer="VISHAY SEMICONDUCTOR OPTO DIVISION", Alternate_Manufacturer_Part_Number=VLMTG1300-GS08, Manufacturer="OSRAM OPTO SEMICONDUCTORS", Manufacturer_Part_Number="LG Q396-PS-35", Package=0603
LD2: library part MCD-00590, "LED Orange, 0603 SMD, Forward Voltage Min=1.6V, Max=2.4V", Alternate_Manufacturer="VISHAY SEMICONDUCTOR OPTO DIVISION", Alternate_Manufacturer_Part_Number=VLMO1300-GS08, Manufacturer="OSRAM OPTO SEMICONDUCTORS", Manufacturer_Part_Number="LO Q976-PS-25", Package=0603
LD3: library part MCD-00587, "LED Red, 0603 SMD, 2V Forward Voltage", Alternate_Manufacturer="OSRAM OPTO SEMICONDUCTORS", Alternate_Manufacturer_Part_Number="LS Q976-NR-1", Manufacturer=VISHAY, Manufacturer_Part_Number=VLMS1300-GS08, Package=0603
LD4: library part MCD-00585, "LED Blue, 0603 SMD, Forward Voltage Min=2,8V, Max=3,8V", Alternate_Manufacturer=EVERLIGHT, Alternate_Manufacturer_Part_Number=19-217-BHC-ZL1M2RY-3T-V4, Manufacturer="OSRAM OPTO SEMICONDUCTORS", Manufacturer_Part_Number="LB Q39G-L2OO-35-1", Package=0603
LD5: library part MCD-00589, "LED Green, 0603 SMD, Fw Voltage = 2.8V - 3.6V", Alternate_Manufacturer="OSRAM OPTO SEMICONDUCTORS", Alternate_Manufacturer_Part_Number="LG Q396-PS-35", Manufacturer=VISHAY, Manufacturer_Part_Number=VLMTG1300-GS08, Package=0603
LD8 LD9: library part MCD-02631, "LED Bicolor, Green/Red, 2V, 20mA,  4-PLCC", Manufacturer="WURTH ELEKTRONIK", Manufacturer_Part_Number=150141SV73110, Package=4-PLCC
Q1: library part MCD-01969, "Transistor, N-channel enhancement mode field-effect transistor", Alternate_Manufacturer=N/A, Manufacturer=NEXPERIA, Manufacturer_Part_Number=BSN20BK, Package=SOT23-3
Q2 Q3: library part MCD-01494, "MOSFET, P-Channel , Vds: -20V, Id: -2.4A, Vgs(th): -1.5V, Vgs(max): +/-8V, Rdson:100mohm@Vgs=-1.8V", Alternate_Manufacturer="ON SEMICONDUCTOR", Alternate_Manufacturer_Part_Number=FDN304PZ, Manufacturer_Part_Number=FDN304P, Package=SOT23-3
Q4 Q5: library part MCD-02152, "Dual N-channel 30 V, 0.016 Ω typ., 40 A, STripFET™ H5 Power MOSFET", Alternate_Manufacturer=N/A, Manufacturer=STMICROELECTRONICS, Manufacturer_HQ_COO=EU, Package=PowerFLAT-8
Q6: library part MCD-00073, "NPN Bipolar Transistor", Manufacturer="ON SEMICONDUCTOR", Manufacturer_Part_Number=BSR14, Package=SOT23
R1 R2 R3 R36 R41 R44 R51 R55 R63 R82 R83 R84 R103 R132 R134 R135 R136: library part MCD-00059, "Resistor,100K,0402,1%,1/16W", Alternate_Manufacturer=YAGEO, Alternate_Manufacturer_Part_Number=RT0402FRE07100KL, Manufacturer_Part_Number=RC0402FR-07100KL, Package=0402
R4 R5 R6 R7 R8 R9: library part MCD-00066, "Resistor,22R,0603,1%,1/10W", Manufacturer=YAGEO, Manufacturer_Part_Number=RC0603FR-0722RL, Package=0603
R10: library part MCD-00220, "Resistor,10K,0603,1%,1/10W", Manufacturer=YAGEO, Manufacturer_Part_Number=RC0603FR-0710KL, Package=0603
R11 R12 R13 R16 R18: library part MCD-00063, "Resistor,47K,0402,1%,1/16W", Manufacturer=YAGEO, Manufacturer_Part_Number=RC0402FR-0747KL, Package=0402
R14: library part MCD-00493, "Resistor,56K,0402,1%,1/16W", Manufacturer=YAGEO, Manufacturer_Part_Number=RC0402FR-0756KL, Package=0402
R15: library part MCD-00443, "Resistor,27K,0402,1%,1/16W", Manufacturer=YAGEO, Manufacturer_Part_Number=RC0402FR-0727KL, Package=0402
R17 R19 R29 R30 R32 R35 R39 R42 R53 R65 R66 R67 R70 R85 R93 R101 R102 R104 R108 R122: library part MCD-00053, "Resistor,10K,0402,1%,1/16W", Manufacturer=YAGEO, Manufacturer_Part_Number=RC0402FR-0710KL, Package=0402
R20 R21 R96: library part MCD-00056, "Resistor,0R,0603,5%,1/10W", Manufacturer=YAGEO, Manufacturer_Part_Number=RC0603JR-070RL, Package=0603
R22 R24 R25: library part MCD-00507, "Resistor,680R,0402,1%,1/16W", Manufacturer=YAGEO, Manufacturer_Part_Number=RC0402FR-07680RL, Package=0402
R23: library part MCD-00528, "Resistor,820R,0603,1%,1/10W", Manufacturer=YAGEO, Manufacturer_Part_Number=RC0603FR-07820RL, Package=0603
R26 R27: library part MCD-00062, "Resistor,330R,0402,1%,1/16W", Manufacturer=YAGEO, Manufacturer_Part_Number=RC0402FR-07330RL, Package=0402
R28 R31 R33 R37 R105 R106: library part MCD-00455, "Resistor,33R,0402,1%,1/16W", Manufacturer=YAGEO, Manufacturer_Part_Number=RC0402FR-0733RL, Package=0402
R34: library part MCD-00068, "Resistor,1K5,0402,1%,1/16W", Manufacturer=YAGEO, Manufacturer_Part_Number=RC0402FR-071K5L, Package=0402
R38 R43 R49 R88 R89 R95 R99 R100 R107 R109 R114 R115 R116 R117 R118 R119 R120: library part MCD-00052, "Resistor,0R,0402,5%,1/16W", Manufacturer=YAGEO, Manufacturer_Part_Number=RC0402JR-070RL, Package=0402
R40: library part MCD-00723, "Resistor,12K1,0402,1%,1/16W", Manufacturer=YAGEO, Manufacturer_Part_Number=RC0402FR-0712K1L, Package=0402
R45 R48 R64 R74: library part MCD-00333, "Resistor, 5K1, 0402, +/-1%, 1/16W", Alternate_Manufacturer=N/A, Manufacturer=YAGEO, Manufacturer_Part_Number=RC0402FR-075K1L, Package=0402
R46 R47 R133 R137 R138 R139: library part MCD-00059, "Resistor, 100K, 0402, +/-1%, 1/16W", Manufacturer=YAGEO, Manufacturer_Part_Number=RC0402FR-07100KL, Package=0402
R50 R54: library part MCD-00441, "Resistor,270R,0402,1%,1/16W", Manufacturer=YAGEO, Manufacturer_Part_Number=RC0402FR-07270RL, Package=0402
R52: library part MCD-00358, "Resistor,10R,0402,1%,1/16W", Manufacturer=YAGEO, Manufacturer_Part_Number=RC0402FR-0710RL, Package=0402
R56: library part MCD-00442, "Resistor,270R,0603,1%,1/10W", Manufacturer=YAGEO, Manufacturer_Part_Number=RC0603FR-07270RL, Package=0603
R57 R62 R73: library part MCD-00056, "Resistor, 0R, 0603, +/-5%, 1/10W", Manufacturer=YAGEO, Manufacturer_Part_Number=RC0603JR-070RL, Package=0603
R58: library part MCD-00067, "Resistor, 100R, 0402, +/- 1%, 1/16W", Manufacturer=YAGEO, Manufacturer_Part_Number=RC0402FR-07100RL, Package=0402
R59 R130: library part MCD-02665, "Resistor, 1K, 0402, +/-0.1%, 1/16W, +/-25ppm/°C", Manufacturer=YAGEO, Manufacturer_Part_Number=RT0402BRD071KL, Package=0402
R60 R131: library part MCD-00062, "Resistor, 330R, 0402, +/-1%, 1/16W", Manufacturer=YAGEO, Manufacturer_Part_Number=RC0402FR-07330RL, Package=0402
R61 R69 R72 R78: library part MCD-00481, "Resistor,47R,0402,1%,1/16W", Manufacturer=YAGEO, Manufacturer_Part_Number=RC0402FR-0747RL, Package=0402
R68 R75 R97 R98: library part MCD-00052, "Resistor, 0R, 0402, +/-5%, 1/16W", Manufacturer=YAGEO, Manufacturer_Part_Number=RC0402JR-070RL, Package=0402
R71: library part MCD-00185, "Resistor,3K,0402,1%,1/16W", Manufacturer=YAGEO, Manufacturer_Part_Number=RC0402FR-073KL, Package=0402
R76: library part MCD-00057, "Resistor, 2K2, 0402, +/-1%, 1/16W", Manufacturer=YAGEO, Manufacturer_Part_Number=RC0402FR-072K2L, Package=0402
R77 R79: library part MCD-00345, "Resistor, 20R, 0603, +/-1%, 1/10W", Manufacturer=YAGEO, Manufacturer_Part_Number=RC0603FR-0720RL, Package=0603
R80 R81: library part MCD-00068, "Resistor, 1K5, 0402, +/-1%, 1/16W", Manufacturer=YAGEO, Manufacturer_Part_Number=RC0402FR-071K5L, Package=0402
R86: library part MCD-00409, "Resistor, 1K8, 0402, +/-1%, 1/16W", Manufacturer=YAGEO, Manufacturer_Part_Number=RC0402FR-071K8L, Package=0402
R87: library part MCD-00185, "Resistor, 3K, 0402, +/-1%, 1/16W", Manufacturer=YAGEO, Manufacturer_Part_Number=RC0402FR-073KL, Package=0402
R90: library part MCD-00061, "Resistor,1K,0402,1%,1/16W", Manufacturer=YAGEO, Manufacturer_Part_Number=RC0402FR-071KL, Package=0402
R91: library part MCD-00182, "Resistor,1M,0402,1%,1/16W", Manufacturer=YAGEO, Manufacturer_Part_Number=RC0402FR-071ML, Package=0402
R92 R94: library part MCD-00485, "Resistor,51R,0402,1%,1/16W", Manufacturer=YAGEO, Manufacturer_Part_Number=RC0402FR-0751RL, Package=0402
R110 R111 R112 R113: library part MCD-00565, "Resistor,49R9,0402,1%,1/16W", Manufacturer=YAGEO, Manufacturer_Part_Number=RC0402FR-0749R9L, Package=0402
R121: library part MCD-02151, "Current Detection Resistor, 0R047, 0805, 1%, 1/4W", Alternate_Manufacturer=N/A, Manufacturer=YAGEO, Manufacturer_Part_Number=RL0805FR-7W0R047L, Package=0805
R123: library part MCD-00433, "Resistor,2K4,0402,1%,1/16W", Manufacturer=YAGEO, Manufacturer_Part_Number=RC0402FR-072K4L, Package=0402
R124: library part MCD-01171, "Resistor,49K9,0603,1%", Manufacturer=YAGEO, Manufacturer_Part_Number=RC0603FR-0749K9L, Package=0603
R125: library part MCD-00458, "Resistor,330K,0603,1%,1/10W", Manufacturer=YAGEO, Manufacturer_Part_Number=RC0603FR-07330KL, Package=0603
R126: library part MCD-00430, "Resistor,22K,0603,1%,1/10W", Manufacturer=YAGEO, Manufacturer_Part_Number=RC0603FR-0722KL, Package=0603
R127: library part MCD-00222, "Resistor,47K,0603,1%,1/10W", Manufacturer=YAGEO, Manufacturer_Part_Number=RC0603FR-0747KL, Package=0603
R128: library part MCD-00381, "Resistor, 1K3, 0402, +/-1%, 1/16W", Manufacturer=YAGEO, Manufacturer_Part_Number=RC0402FR-071K3L, Package=0402
R129: library part MCD-02455, "Resistor, 3K9, 0402, +/-1%, 1/16W, +/-100ppm/°C", Manufacturer=YAGEO, Manufacturer_Part_Number=RC0402FR-073K9L, Package=0402
SB1 SB2 SB3 SB4 SB5 SB6 SB7 SB8 SB9 SB10 SB11 SB12 SB13 SB14 SB15 SB16 SB17 SB18 SB19 SB20 SB21 SB22 SB23 SB24 SB25 SB28 SB29: library part MCD-00071, "Resistor, 0R, SB0603, 5%, 0.1W", Manufacturer=YAGEO, Manufacturer_HQ_COO=Unknown, Manufacturer_Part_Number=RC0603JR-070RL, Package=0603
SW1: library part MCD-00566, "Mechanical Slide Switches 1K2 BLK ACT GOLD STRT MNT", Manufacturer=EAO, Manufacturer_Part_Number=09.03290.01, Package=2.5x10mm
TP2 TP3 TP4: library part MCD-00177, "Test Point 2mm", Manufacturer=n/a
TP5: library part MCD-00074, "Test Point 1mm", Manufacturer=N/A, Manufacturer_HQ_COO=Unknown, Manufacturer_Part_Number=n/a
TP13: library part MCD-00074, "Test Point 1mm", Manufacturer=n/a, Manufacturer_HQ_COO=Unknown
U1 U2 U3 U4 U16: library part MCD-00136, "Dual Transil array for ESD protection", Manufacturer=STMICROELECTRONICS, Manufacturer_HQ_COO=EU, Package=SOT323-5
U5 U7: library part MCD-00667, "4-line ESD protection for high speed lines", Manufacturer=STMICROELECTRONICS, Manufacturer_HQ_COO=EU, Package=uQFN-10
U6: library part MCD-00581, "LDO Linear Voltage Regulator IC Positive Adjustable 1 Output Adjustable 1.3A 6-DFN (3x3)", Manufacturer=STMICROELECTRONICS, Manufacturer_HQ_COO=EU, Package=DFN-6
U8: library part MCD-00088, "IC REG LDO 5V 0.8A SOT223", Manufacturer=STMICROELECTRONICS, Manufacturer_HQ_COO=EU, Package=SOT223-4
U9: library part MCD-01025, "LDO, 3.3V, 1.3A, Very low quiescent current BiCMOS voltage regulator", Manufacturer=STMICROELECTRONICS, Manufacturer_HQ_COO=EU, Package=DFN-6
U10 U14 U17: library part MCD-00170, "ESD protection 6V1", Manufacturer=STMICROELECTRONICS, Manufacturer_HQ_COO=EU, Manufacturer_Part_Number=ESDALC6V1-1U2, Package=ST0201
U11: library part MCD-00719, "10/100M RMII Ethernet transceiver", Manufacturer=MICROCHIP, Package=VQFN-24
U12: library part MCD-00250, "Very low capacitance ESD protection , 4 lines", Manufacturer=STMICROELECTRONICS, Package=SOT23-6
U13 U32: library part MCD-01207, "High power Transient voltage suppressor:25V/35A EOS and ESD transients protection.", Manufacturer=STMICROELECTRONICS, Manufacturer_HQ_COO=EU, Manufacturer_Part_Number=ESDA25P35-1U1M, Package=QFN1610
U15: library part MCD-00082, "White LED power supply for large display backlight, QFN8", Manufacturer=STMICROELECTRONICS, Manufacturer_HQ_COO=EU, Package=QFN-8
U18: library part MCD-00247, "Quad Bidir ESD protection", Manufacturer=STMICROELECTRONICS, Manufacturer_HQ_COO=EU, Package=SOT23-6
U19: library part MCD-00649, "Common mode filter with ESD protection for USB 2.0 interface", Manufacturer=STMICROELECTRONICS, Manufacturer_HQ_COO=EU, Package=QFN-6
U20: library part MCD-02122, "MEMS sensors , omnidirectionnal digital microphone", Manufacturer=STMICROELECTRONICS, Manufacturer_HQ_COO=EU, Manufacturer_Part_Number=MP23DB01HPTR, Package=RHLGA-5
U21: library part MCD-00159, "500mA, Enhanced single channel power switches with active high enable pin", Manufacturer=STMICROELECTRONICS, Package=SOT23-5
U22: library part MCD-02706, "STM32F723IEK  (STM32F7) BGA176", Manufacturer=STMICROELECTRONICS, Manufacturer_Part_Number=STM32F723IEK6, Package=BGA-176
U23: library part MCD-00317, "Low voltage high bandwidth quad SPDT switch", Manufacturer=STMICROELECTRONICS, Manufacturer_HQ_COO=EU, Package=LQFP-64
U24: library part MCD-02514, "LDO, 3.3V, 300mA, High input voltage: 2.5V to 28V, SOT23-5L", Alternate_Manufacturer=N/A, Manufacturer=STMICROELECTRONICS, Package=SOT23-5
U25: library part MCD-03825, "Audio Codec, Ultra Low-Power Codec for Portable Audio Applications", Manufacturer="CIRRUS LOGIC"
U26 U27: library part MCD-01945, "4-bit dual supply translating transceiver with configurable voltage translation; 3-state", Alternate_Manufacturer=N/A, Manufacturer=NEXPERIA, Manufacturer_Part_Number=74AVC4TD245BQ,115, Package=DHVQFN-16
U28: library part MCD-02379, "MCU, Arm Cortex-M33, 250MHz, 32-bit MCU, 2MB Flash, 640KB SRAM, Crypto", Alternate_Manufacturer=N/A, Manufacturer=STMICROELECTRONICS, Package=UFBGA-176+25
U29: library part MCD-00246, "Memory,Octo-SPI-NOR,512Mb,2048x16,133MHz,3V,DTR,BGA24, CMOS MXSMIO", Manufacturer=MACRONIX, Package=BGA-24
U30: library part MCD-02130, "USB Type-C Port Protection for USB DRP Power Delivery, PPS compliant", Alternate_Manufacturer=N/A, Manufacturer=STMICROELECTRONICS, Manufacturer_HQ_COO=EU, Package=QFN-20
U31: library part MCD-00163, "Very low capacitance ESD protection", Manufacturer=STMICROELECTRONICS, Package=SOT23-6
U34: library part MCD-02532, "eFuse with Fast Overvoltage Protection 2.7V to 18V 4A 34mOhm 8-Pin WSON", Manufacturer="TEXAS INSTRUMENTS", Package=WSON-8
X1: library part MCD-01036, "Crystal, 24MHz, 6pF, +/-20ppm, 80R, 2x1.6mm", Manufacturer=NDK, Manufacturer_Part_Number=NX2016SA-24MHZ-EXS00A-CS10820, Package=2x1.6mm
X2: library part MCD-02291, "Crystal, 32.768kHz, 9pF, +/-20ppm, 70KR, 1.6x1mm", Manufacturer=NDK, Manufacturer_Part_Number=NX1610SE-32.768KHZ-EXS00A-MU01499, Package=1.6x1mm
X3: library part MCD-00597, "Oscillator 25Mhz, +-50ppm, Vcc:3.3V typ, square wave: [0.1Vcc;0.9Vcc], Enable pin, SMD", Alternate_Manufacturer=NDK, Alternate_Manufacturer_Part_Number="NZ2520SB 25MHz END4869B", Manufacturer_Part_Number=NZ2520SH-25MHZ-END4869C, Package=2.5x2mm

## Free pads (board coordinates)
  round 0.508 on Mech16: 1(10.598,-32.231) 1(59.446,-32.231)

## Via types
v1: diameter 0.55, hole 0.35, Top Layer to Bottom Layer, tented both sides, 748 vias
v2: diameter 0.4, hole 0.2, Top Layer to Bottom Layer, tented both sides, 203 vias
v3: diameter 0.6, hole 0.3, Top Layer to Bottom Layer, tented both sides, 9 vias
v4: diameter 0.55, hole 0.33, Top Layer to Bottom Layer, tented both sides, 1 vias

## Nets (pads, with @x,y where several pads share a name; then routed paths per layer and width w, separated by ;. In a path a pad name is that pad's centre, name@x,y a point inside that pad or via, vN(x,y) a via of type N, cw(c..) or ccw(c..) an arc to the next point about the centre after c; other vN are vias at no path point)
1V8: JP2.3 L6.1 L7.1 L8.1 SB10.2 TP2.1 | length 18.6
  Top Layer w0.3: v1(52.4,72.925) 52.4,72.9 53.275,72.025 56.6,72.025 v1(58.975,69.65)
  Bottom Layer w0.3: v1(52.4,72.925) 52.4,72.5 52.15,72.25 52.15,70.75 52.4,70.5 52.75,70.5 L7.1@52.925,70.325 ; L6.1@58.725,70.225 58.8,70.225 58.975,70.05 v1(58.975,69.65) ; v1(63.05,81.275) 63.098,81.227 64.477,81.227 64.95,81.7 L8.1@64.95,83.125
  Bottom Layer w0.5: SB10.2@2.8,68.275 2.825,68.3 v1(2.825,69.275) v1(2.825,69.975) 2.835,69.985 2.835,71.435 TP2.1@2.85,71.45
3V3: C25.1 C67.2 C107.2 CN2.2 CN2.19 CN6.6 CN6.12 CN14.5 JP2.1 L1.2 L5.1 LD1.1 LD2.1 LD3.1 LD4.1 Q3.2 R17.1 R27.2 R56.2 R93.1 R99.1 SB1.1 SB13.2 SB14.1 TP4.1 U6.6 U23.2 X3.4 | length 32
  Top Layer w0.3: R56.2@11.95,3.22 13.895,3.22 v1(13.9,3.225) ; v1(54.975,29.475) 55.75,29.475 L1.2@55.85,29.375 ; R27.2@70.428,45.85 70.509,45.932 70.509,46.409 v1(70.975,46.875) ; LD1.1@73.915,47.99 v1(74.692,47.99) ; LD2.1@73.915,50.04 v1(74.692,50.04) ; LD3.1@73.915,52.115 v1(74.692,52.115) ; LD4.1@73.915,54.24 v1(74.692,54.24)
  Bottom Layer w0.1: v1(37.725,54.15) 38.825,54.15 SB14.1@39,54.325
  Bottom Layer w0.2: U23.2@69.991,87.194 C67.2@71.191,87.194
  Bottom Layer w0.3: v1(4.65,40.325) 4.681,40.356 4.681,40.895 4.786,41 R99.1@4.825,41 4.93,40.895 5.131,40.895 5.201,40.825 5.975,40.825 6.325,40.475 Q3.2@6.325,40.275 ; SB13.2@7.7,58.45 10.023,58.45 10.873,57.6 TP4.1@10.975,57.6 ; L5.1@55.3,83.125 55.3,83.8 57.525,86.025 v1(63.125,86.025) ; X3.4@61.325,52.325 61.525,52.525 C107.2@62.6,52.525 R93.1@62.6,51.65 v1(63.35,51.65) ; SB1.1@62.6,70.2 62.852,69.948 v1(63.527,69.948) ; CN14.5@69.41,47.735 69.77,47.375 70.213,47.375 70.713,46.875 v1(70.975,46.875) ; C67.2@71.175,87.21 v1(71.175,87.8)
  other v1: 9.3,59.225 9.3,60 2.875,62.1 3.575,62.1
3V3_LCD: C4.2 C50.1 C118.2 CN4.9 CN7.26 Q3.3 R99.2 | length 45.5
  Top Layer w0.3: C50.1@22.15,18.825 22.175,18.825 22.28,18.93 22.28,18.955 22.62,19.295 v1(22.62,19.43) 22.572,19.478 22.572,19.655 22.54,19.687 22.54,19.913 CN7.26@22.54,20.175 ; CN4.9@46.725,85.35 47.225,85.35 47.45,85.575 47.45,86.175 47.175,86.45 47.175,87.575 47.92,88.32 47.92,88.545 C4.2@48.025,88.65 v1(48.025,89.225)
  Signal Layer 2 w0.5: 9.55,40.95 9.55,40.5 ; v1(9.55,42.35) 9.55,40.5 ; v1(15.3,18.8) 15.3,23.8 14.7,24.4 14.7,32.094 11.847,34.947 11.847,38.203 9.55,40.5
  Signal Layer 3 w0.5: v1(15.3,18.8) 18.45,18.8 19.08,19.43 v1(22.62,19.43)
  Bottom Layer w0.3: v1(3.45,42.625) 4.1,42.625 4.625,42.1 4.625,42.005 4.73,41.9 R99.2@4.825,41.9 4.93,42.005 5.03,42.005 5.5,42.475 Q3.3@7.275,42.475 ; C118.2@9.55,41.775 v1(9.55,42.35)
3V3_STLK: C1.1 C2.1 C5.1 C6.1 C7.1 C8.1 C9.1 C10.1 C11.1 C12.1 C13.1 C14.1 C15.1 C16.1 C17.1 C18.1 C19.1 C66.2 C90.2 C92.2 CN11.1 JP1.1 LD8.4 LD9.4 R1.2 R82.2 R83.2 R84.2 R85.2 R134.1 R135.2 R136.2 R138.1 U22.C1 U22.C5 U22.C6 U22.C7 U22.C8 U22.C9 U22.F3 U22.G3 U22.G13 U22.H13 U22.J12 U22.J13 U22.K4 U22.N8 U22.N9 U22.N10 U22.P1 U22.R1 U24.1 U26.1 U26.2 U26.7 U26.15 U27.1 U27.2 | length 59.3
  Top Layer w0.3: C15.1@19.175,81.275 20.675,81.275 v2(21,81.6) ; C5.1@19.3,88.425 19.3,88.45 19.405,88.555 19.43,88.555 19.625,88.75 v2(20.35,88.75) ; C1.1@19.3,89.45 19.35,89.4 v2(20.35,89.4) ; v1(22.025,71.2) 22.9,71.2 v1(23.775,72.075) ; C12.1@22.25,84.125 22.281,84.094 22.281,83.569 v2(22.3,83.55) ; C9.1@22.25,84.925 22.281,84.956 22.281,85.481 v2(22.3,85.5) ; v2(22.3,82.9) 23,82.9 C14.1@23.025,82.875 ; C16.1@22.95,80.4 v2(22.95,80.95) ; C17.1@24,80.4 24.025,80.4 24.13,80.505 24.13,80.803 24.25,80.923 v2(24.25,80.95) ; v1(24.8,75.025) 26.448,75.025 26.475,74.998 26.652,74.998 v1(26.7,74.95) ; C7.1@24.8,88.1 v2(25.55,88.1) ; v2(24.9,80.95) 24.913,80.937 24.913,80.412 C18.1@24.925,80.4 ; v2(25.55,80.95) 25.55,80.923 25.72,80.753 25.72,80.505 25.825,80.4 C19.1@25.85,80.4 ; v2(26.2,88.1) 26.2,89.05 C2.1@26.225,89.075 ; v2(26.85,88.1) 27.45,88.1 C6.1@27.475,88.125 ; C10.1@27.6,84.75 27.661,84.811 28.111,84.811 v2(28.8,85.5) ; C8.1@27.631,85.694 C8.1@27.6,85.725 27.6,85.7 27.705,85.595 27.73,85.595 27.806,85.519 28.131,85.519 v2(28.15,85.5) ; v2(28.8,83.55) 28.819,83.531 29.294,83.531 C13.1@29.375,83.45 ; v2(28.8,84.2) 28.827,84.2 28.881,84.254 29.27,84.254 29.375,84.359 C11.1@29.375,84.375
  Top Layer w0.5: v1(11.165,103.725) 11.165,102.51 LD8.4@11.175,102.5 ; v1(17.1,103.725) 17.1,102.51 LD9.4@17.11,102.5
  Signal Layer 2 w0.3: v1(23.775,72.075) 24.8,73.1 v1(24.8,75.025)
  Signal Layer 3 w0.3: v1(40.95,71.775) 40.95,72.325
  Signal Layer 4 w0.3: v1(28.85,71.25) 29.321,71.25 30.146,72.075 v1(30.625,72.075) ; v1(30.55,69.525) 30.55,71.932 30.625,72.007 v1(30.625,72.075) ; v1(31.6,74.975) 30.625,74 v1(30.625,72.075)
  Bottom Layer w0.12: v1(40.95,71.775) 41.625,71.775 R138.1@41.65,71.75
  Bottom Layer w0.25: v2(20.35,88.75) U22.P1@20.675,88.425 ; v2(20.35,89.4) U22.R1@20.675,89.075 ; U22.C1@20.675,81.275 v2(21,81.6) ; U22.F3@21.975,83.225 v2(22.3,82.9) ; U22.G3@21.975,83.875 v2(22.3,83.55) ; v2(22.3,85.5) U22.K4@22.625,85.825 ; v2(22.95,80.95) U22.C5@23.275,81.275 ; v2(23.6,80.95) U22.C6@23.925,81.275 ; v2(24.25,80.95) U22.C7@24.575,81.275 ; v2(24.9,80.95) U22.C8@25.225,81.275 ; U22.N8@25.225,87.775 v2(25.55,88.1) ; v2(25.55,80.95) U22.C9@25.875,81.275 ; U22.N9@25.875,87.775 v2(26.2,88.1) ; U22.N10@26.525,87.775 v2(26.85,88.1) ; U22.J12@27.825,85.175 v2(28.15,85.5) ; U22.G13@28.475,83.875 v2(28.8,83.55) ; U22.H13@28.475,84.525 v2(28.8,84.2) ; U22.J13@28.475,85.175 v2(28.8,85.5)
  Bottom Layer w0.3: v1(17.4,81.25) 18.17,81.25 18.275,81.355 R85.2@18.275,81.375 ; v1(22.025,71.2) C90.2@22.75,71.2 22.775,71.2 22.95,71.025 U27.1@23.85,71.025 ; v1(23.775,72.075) 24.3,72.075 U27.2@24.3,71.975 ; R82.2@24.175,74.275 R84.2@25.197,74.275 ; v1(24.8,75.025) 24.825,75.025 25.092,74.758 25.092,74.38 R84.2@25.197,74.275 ; R84.2@25.25,74.275 R84.2@25.197,74.275 ; R83.2@26.325,74.275 26.385,74.275 26.7,74.59 v1(26.7,74.95) ; v1(28.85,71.25) 28.881,71.219 29.481,71.219 C92.2@29.55,71.15 29.575,71.15 29.7,71.025 U26.1@30.6,71.025 ; R134.1@30.525,74.275 v1(30.525,74.975) ; v1(30.55,69.525) 31.05,69.525 U26.15@31.05,69.575 ; v1(30.625,72.075) 31.05,72.074 U26.2@31.05,71.975 ; R135.2@31.6,74.275 v1(31.6,74.975) ; R1.2@32.675,74.275 v1(32.675,74.975) ; U26.7@33.55,71.975 33.55,72.225 33.837,72.512 v1@34.187,72.512 ; R136.2@33.75,74.275 33.855,74.17 34.105,74.17 34.5,73.775 34.5,72.851 34.187,72.538 v1@34.187,72.512 ; v1(34.225,72.55) v1@34.187,72.512
  Bottom Layer w0.5: v1(40.75,87.1) C66.2@41.6,87.1 41.6,86.975 41.925,86.65 U24.1@41.925,85.475
5V: C28.2 CN3.6 CN3.15 CN14.4 JP4.2 JP4.4 JP4.6 JP4.8 R19.1 R23.1 R49.1 R64.2 R103.1 SB28.1 U9.6 | length 34.9
  Top Layer w0.25: v1(2.15,49.7) 2.163,49.713 R23.1@2.81,49.713
  Top Layer w0.3: v1(3.425,14.5) R49.1@5.85,14.5
  Signal Layer 3 w0.4: v1(5.15,92.175) 11.175,92.175 12.575,93.575 20.175,93.575 22.019,91.731 23.581,91.731 v1(24.3,92.45)
  Signal Layer 3 w0.8: v1(5.15,79.3) CN3.15@7.65,79.3 CN3.6@9.65,81.3
  Bottom Layer w0.3: R103.1@14.125,36.275 v1(14.9,36.275) ; R64.2@24.3,91.875 v1(24.3,92.45) ; v1(38.325,1.675) 38.33,1.68 SB28.1@39.425,1.68
  Bottom Layer w0.8: CN14.4@72.615,45.195 72.62,45.2 74.3,45.2 v1(74.725,44.775) v1(75.675,44.775)
  other v1: 38.325,0.85 37.45,1.675 14.1,5.15 14.5,5.875 13.675,6.05 76.15,12.975 75.075,13.025 75.55,14.05 2.825,34.15 2.825,34.95 2.825,35.75 10.4,35.85 10.4,36.65 10.4,37.45 3.125,48.5 2.125,48.725 2.975,56.55 3.675,56.55
5V_STLK: C60.2 C64.2 JP4.1 R87.1 U21.1 U34.5 U34.6 | length 12
  Top Layer w0.8: JP4.1@2.5,46.505 2.75,46.755 4.055,46.755 v1(4.425,47.125) v1(4.425,46.425) 2.58,46.425 JP4.1@2.5,46.505
  Bottom Layer w0.12: R87.1@35.77,76.8 35.575,76.995 R87.1@35.575,77.025 35.575,77.105 35.77,77.3 U34.6@36.725,77.3
  Bottom Layer w0.2: R87.1@35.77,76.8 U34.5@36.725,76.8
  Bottom Layer w0.5: U34.5@36.725,76.675 36.725,75.65 36.82,75.555 36.82,74.969 36.9,74.889 v1(36.9,74.875) ; v1(40.15,68.925) 40.95,68.925 40.975,68.95 C60.2@41.025,68.9 41.15,68.9 41.22,68.83 41.22,68.705 41.55,68.375 U21.1@42.575,68.375
  other v1: 29.55,46.95 30.25,46.95 36.175,74.875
